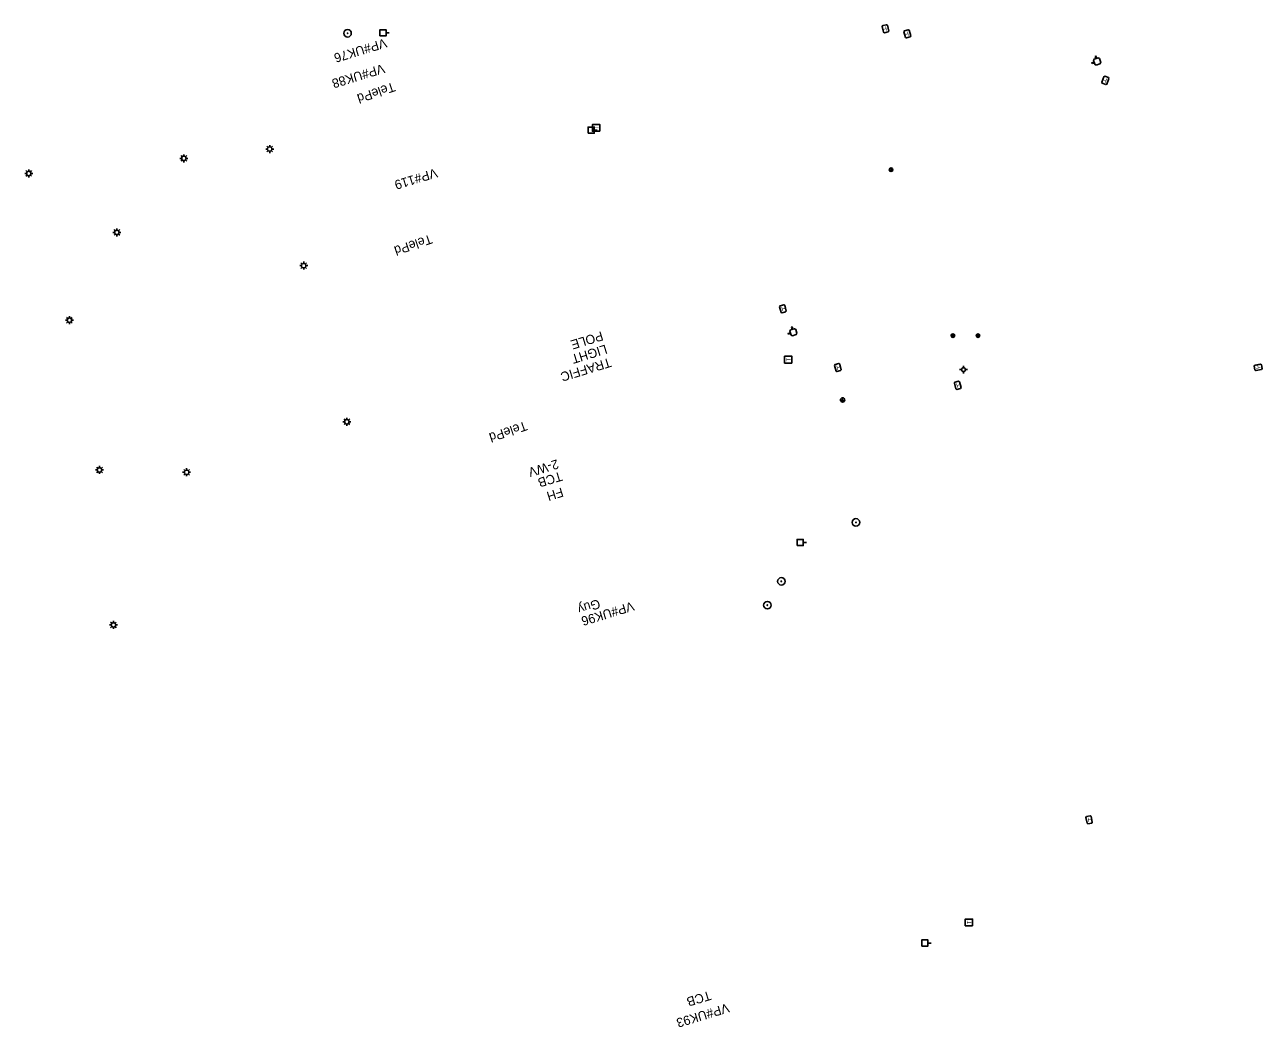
# Model space of a CAD drawing. Extents: x 3872070 to 3879223, y 293944 to 310567.
# Drawn here: x 3874077.6 to 3874479.2, y 307334.8 to 307660.2 of the extents above; entities that cross this region are included whole.
import ezdxf

# ---------------------------------------------------------------- set-up
doc = ezdxf.new("R2010")
doc.units = 0
for name, color, linetype in [('Level 34', 7, 'Continuous'), ('Level 35', 7, 'Continuous'), ('Level 37', 7, 'Continuous'), ('Level 39', 7, 'Continuous'), ('Level 4', 7, 'Continuous'), ('Level 5', 7, 'Continuous'), ('Level 6', 7, 'Continuous'), ('Level 7', 7, 'Continuous'), ('Level 9', 7, 'Continuous')]:
    doc.layers.add(name, color=color, linetype=linetype)

msp = doc.modelspace()

# ---------------------------------------------------------------- linework, layer by layer
at = {"layer": 'Level 4'}
for p, q in [((3874194.86, 307657.58), (3874195.86, 307657.58)), ((3874262.37, 307626.03), (3874263.37, 307626.03)), ((3874156.34, 307619.88), (3874155.77, 307619.88)), ((3874156.55, 307620.39), (3874156.15, 307620.8)), ((3874157.07, 307620.6), (3874157.07, 307621.18)), ((3874157.58, 307620.39), (3874157.98, 307620.8)), ((3874157.79, 307619.88), (3874158.37, 307619.88)), ((3874128.51, 307616.85), (3874127.93, 307616.85)), ((3874128.72, 307617.36), (3874128.31, 307617.77)), ((3874128.31, 307615.93), (3874128.72, 307616.33)), ((3874129.23, 307617.57), (3874129.23, 307618.15)), ((3874129.23, 307616.12), (3874129.23, 307615.55)), ((3874129.74, 307617.36), (3874130.15, 307617.77)), ((3874130.15, 307615.93), (3874129.74, 307616.33)), ((3874129.96, 307616.85), (3874130.53, 307616.85)), ((3874156.15, 307618.96), (3874156.55, 307619.37)), ((3874157.07, 307619.16), (3874157.07, 307618.58)), ((3874157.98, 307618.96), (3874157.58, 307619.37)), ((3874078.16, 307611.95), (3874077.58, 307611.95)), ((3874078.37, 307612.47), (3874077.96, 307612.87)), ((3874078.88, 307612.68), (3874078.88, 307613.25)), ((3874079.4, 307612.47), (3874079.8, 307612.87)), ((3874079.61, 307611.95), (3874080.18, 307611.95)), ((3874077.96, 307611.03), (3874078.37, 307611.44)), ((3874078.88, 307611.23), (3874078.88, 307610.65)), ((3874079.8, 307611.03), (3874079.4, 307611.44)), ((3874106.76, 307592.82), (3874106.19, 307592.82)), ((3874106.97, 307593.33), (3874106.57, 307593.74)), ((3874106.57, 307591.9), (3874106.97, 307592.3)), ((3874107.48, 307593.54), (3874107.48, 307594.12)), ((3874107.48, 307592.09), (3874107.48, 307591.52)), ((3874108, 307593.33), (3874108.4, 307593.74)), ((3874108.4, 307591.9), (3874108, 307592.3)), ((3874108.21, 307592.82), (3874108.79, 307592.82)), ((3874168.11, 307582.75), (3874168.11, 307583.33)), ((3874167.39, 307582.03), (3874166.81, 307582.03)), ((3874167.6, 307582.54), (3874167.19, 307582.95)), ((3874167.19, 307581.11), (3874167.6, 307581.52)), ((3874168.11, 307581.3), (3874168.11, 307580.73)), ((3874168.62, 307582.54), (3874169.03, 307582.95)), ((3874169.03, 307581.11), (3874168.62, 307581.52)), ((3874168.83, 307582.03), (3874169.41, 307582.03)), ((3874091.35, 307564.31), (3874090.78, 307564.31)), ((3874091.56, 307564.82), (3874091.16, 307565.23)), ((3874091.16, 307563.39), (3874091.56, 307563.79)), ((3874092.08, 307565.03), (3874092.08, 307565.61)), ((3874092.08, 307563.58), (3874092.08, 307563.01)), ((3874092.59, 307564.82), (3874093, 307565.23)), ((3874093, 307563.39), (3874092.59, 307563.79)), ((3874092.8, 307564.31), (3874093.38, 307564.31)), ((3874181.39, 307531.35), (3874180.81, 307531.35)), ((3874181.6, 307531.86), (3874181.2, 307532.27)), ((3874182.11, 307532.08), (3874182.11, 307532.65)), ((3874182.63, 307531.86), (3874183.03, 307532.27)), ((3874182.84, 307531.35), (3874183.41, 307531.35)), ((3874181.2, 307530.43), (3874181.6, 307530.84)), ((3874182.11, 307530.63), (3874182.11, 307530.05)), ((3874183.03, 307530.43), (3874182.63, 307530.84)), ((3874101.14, 307515.71), (3874100.56, 307515.71)), ((3874101.35, 307516.22), (3874100.94, 307516.62)), ((3874100.94, 307514.79), (3874101.35, 307515.19)), ((3874101.86, 307516.43), (3874101.86, 307517.01)), ((3874102.38, 307516.22), (3874102.78, 307516.62)), ((3874102.78, 307514.79), (3874102.38, 307515.19)), ((3874102.59, 307515.71), (3874103.16, 307515.71)), ((3874129.6, 307515.47), (3874129.19, 307515.87)), ((3874130.11, 307515.68), (3874130.11, 307516.25)), ((3874130.62, 307515.47), (3874131.03, 307515.87)), ((3874101.86, 307514.98), (3874101.86, 307514.41)), ((3874129.39, 307514.95), (3874128.81, 307514.95)), ((3874129.19, 307514.03), (3874129.6, 307514.44)), ((3874130.11, 307514.23), (3874130.11, 307513.65)), ((3874131.03, 307514.03), (3874130.62, 307514.44)), ((3874130.83, 307514.95), (3874131.41, 307514.95)), ((3874330.23, 307492.16), (3874331.23, 307492.16)), ((3874105.65, 307465.4), (3874105.08, 307465.4)), ((3874105.87, 307465.92), (3874105.46, 307466.32)), ((3874105.46, 307464.48), (3874105.87, 307464.89)), ((3874106.38, 307466.13), (3874106.38, 307466.7)), ((3874106.38, 307464.68), (3874106.38, 307464.1)), ((3874106.89, 307465.92), (3874107.3, 307466.32)), ((3874107.3, 307464.48), (3874106.89, 307464.89)), ((3874107.1, 307465.4), (3874107.68, 307465.4)), ((3874370.7, 307362.14), (3874371.7, 307362.14))]:
    msp.add_line(p, q, dxfattribs=at)
for points in [[(3874192.86, 307656.58), (3874192.86, 307658.58), (3874194.86, 307658.58), (3874194.86, 307656.58)], [(3874260.37, 307625.03), (3874260.37, 307627.03), (3874262.37, 307627.03), (3874262.37, 307625.03)], [(3874328.23, 307491.16), (3874328.23, 307493.16), (3874330.23, 307493.16), (3874330.23, 307491.16)], [(3874368.7, 307361.14), (3874368.7, 307363.14), (3874370.7, 307363.14), (3874370.7, 307361.14)]]:
    msp.add_lwpolyline(points, close=True, dxfattribs=at)
for centre, radius in [((3874182.34, 307657.46), 1.22), ((3874182.34, 307657.46), 0.0992), ((3874182.34, 307657.46), 0.0483), ((3874157.07, 307619.88), 0.725), ((3874129.23, 307616.85), 0.725), ((3874078.88, 307611.95), 0.725), ((3874107.48, 307592.82), 0.725), ((3874168.11, 307582.03), 0.725), ((3874092.08, 307564.31), 0.725), ((3874182.11, 307531.35), 0.725), ((3874101.86, 307515.71), 0.725), ((3874130.11, 307514.95), 0.725), ((3874347.33, 307498.68), 1.22), ((3874347.33, 307498.68), 0.0992), ((3874347.33, 307498.68), 0.0483), ((3874323.12, 307479.55), 1.22), ((3874323.12, 307479.55), 0.0992), ((3874323.12, 307479.55), 0.0483), ((3874318.58, 307471.82), 1.22), ((3874318.58, 307471.82), 0.0992), ((3874318.58, 307471.82), 0.0483), ((3874106.38, 307465.4), 0.725)]:
    msp.add_circle(centre, radius, dxfattribs=at)
at = {"layer": 'Level 5'}
for p, q in [((3874358.72, 307613.87), (3874358.72, 307613.15)), ((3874358.72, 307613.57), (3874358.72, 307612.73)), ((3874358.72, 307613.15), (3874358.72, 307612.43)), ((3874378.79, 307560.03), (3874378.79, 307559.31)), ((3874378.79, 307559.73), (3874378.79, 307558.89)), ((3874378.79, 307559.31), (3874378.79, 307558.59)), ((3874386.93, 307560.03), (3874386.93, 307559.31)), ((3874386.93, 307559.73), (3874386.93, 307558.89)), ((3874386.93, 307559.31), (3874386.93, 307558.59)), ((3874380.97, 307548.27), (3874381.59, 307548.27)), ((3874382.22, 307549.52), (3874382.22, 307548.89)), ((3874382.22, 307547.65), (3874382.22, 307547.02)), ((3874382.84, 307548.27), (3874383.47, 307548.27))]:
    msp.add_line(p, q, dxfattribs=at)
for centre, radius in [((3874358.73, 307613.15), 0.583), ((3874378.79, 307559.31), 0.583), ((3874386.94, 307559.31), 0.583), ((3874382.22, 307548.27), 0.625)]:
    msp.add_circle(centre, radius, dxfattribs=at)
for centre in [(3874358.73, 307613.15), (3874378.79, 307559.31), (3874386.94, 307559.31)]:
    msp.add_arc(centre, 0.417, 270, 90, dxfattribs=at)
at = {"layer": 'Level 6'}
for radius in [0.7, 0.188]:
    msp.add_circle((3874342.98, 307538.44), radius, dxfattribs=at)
at = {"layer": 'Level 7'}
for points in [[(3874264.22, 307625.65), (3874261.82, 307625.65), (3874261.82, 307627.84), (3874264.22, 307627.84)], [(3874326.56, 307550.41), (3874324.17, 307550.41), (3874324.17, 307552.6), (3874326.56, 307552.6)], [(3874385.17, 307367.74), (3874382.77, 307367.74), (3874382.77, 307369.93), (3874385.17, 307369.93)]]:
    msp.add_lwpolyline(points, close=True, dxfattribs=at)
at = {"layer": 'Level 9'}
for p, q in [((3874424.6, 307648.13), (3874423.86, 307647.9)), ((3874423.94, 307647.66), (3874423.86, 307647.9)), ((3874424.68, 307647.9), (3874423.94, 307647.66)), ((3874326.03, 307560.22), (3874325.29, 307559.98)), ((3874325.36, 307559.74), (3874325.29, 307559.98)), ((3874326.1, 307559.98), (3874325.36, 307559.75))]:
    msp.add_line(p, q, dxfattribs=at)
for points in [[(3874357.51, 307660.05), (3874357.95, 307658.19), (3874357.77, 307657.89), (3874356.58, 307657.6), (3874356.27, 307657.79), (3874355.83, 307659.64), (3874356.01, 307659.95), (3874357.21, 307660.23)], [(3874364.56, 307658.43), (3874365.08, 307656.59), (3874364.91, 307656.28), (3874363.73, 307655.95), (3874363.42, 307656.12), (3874362.9, 307657.95), (3874363.07, 307658.26), (3874364.25, 307658.6)], [(3874423.94, 307647.66), (3874424.68, 307647.89), (3874424.6, 307648.13), (3874423.86, 307647.9)], [(3874425.28, 307647.16), (3874426.51, 307647.55), (3874426.74, 307647.99), (3874426.36, 307649.23), (3874425.91, 307649.46), (3874424.68, 307649.07), (3874424.45, 307648.63), (3874424.84, 307647.4)], [(3874424.94, 307649.97), (3874425.18, 307649.23), (3874425.42, 307649.3), (3874425.18, 307650.05)], [(3874429.38, 307642.77), (3874428.74, 307640.97), (3874428.43, 307640.82), (3874427.27, 307641.23), (3874427.12, 307641.55), (3874427.75, 307643.35), (3874428.07, 307643.5), (3874429.23, 307643.09)], [(3874323.02, 307566.86), (3874322.53, 307568.7), (3874322.71, 307569.01), (3874323.89, 307569.32), (3874324.2, 307569.15), (3874324.69, 307567.3), (3874324.51, 307567), (3874323.33, 307566.68)], [(3874325.36, 307559.74), (3874326.11, 307559.98), (3874326.03, 307560.22), (3874325.29, 307559.98)], [(3874326.71, 307559.25), (3874327.94, 307559.64), (3874328.17, 307560.08), (3874327.78, 307561.31), (3874327.34, 307561.54), (3874326.11, 307561.16), (3874325.87, 307560.71), (3874326.26, 307559.48)], [(3874326.37, 307562.06), (3874326.6, 307561.31), (3874326.84, 307561.39), (3874326.61, 307562.13)], [(3874340.87, 307547.81), (3874340.37, 307549.65), (3874340.55, 307549.96), (3874341.73, 307550.28), (3874342.04, 307550.1), (3874342.53, 307548.26), (3874342.35, 307547.95), (3874341.17, 307547.64)], [(3874478.98, 307548.37), (3874477.11, 307547.98), (3874476.82, 307548.18), (3874476.57, 307549.38), (3874476.77, 307549.67), (3874478.63, 307550.06), (3874478.93, 307549.86), (3874479.17, 307548.66)], [(3874379.75, 307542.02), (3874379.25, 307543.86), (3874379.43, 307544.17), (3874380.61, 307544.49), (3874380.92, 307544.31), (3874381.42, 307542.47), (3874381.24, 307542.16), (3874380.06, 307541.85)], [(3874422.33, 307401.05), (3874421.96, 307402.93), (3874422.16, 307403.22), (3874423.36, 307403.46), (3874423.65, 307403.26), (3874424.02, 307401.39), (3874423.83, 307401.1), (3874422.62, 307400.86)]]:
    msp.add_lwpolyline(points, close=True, dxfattribs=at)

# ---------------------------------------------------------------- texts
at = {"layer": 'Level 34'}
for s, rotation, p in [('VP#UK76', 196.9281, (3874194.52, 307655.86)), ('VP#UK88', 196.9281, (3874193.85, 307647.56)), ('VP#119', 196.9281, (3874210.96, 307613.68)), ('Guy', 196.6305, (3874263.8, 307473.82)), ('VP#UK96', 196.9281, (3874274.78, 307473.05)), ('VP#UK93', 196.9281, (3874305.65, 307342.63))]:
    msp.add_text(s, height=3, rotation=rotation, dxfattribs=at).set_placement(p)
at = {"layer": 'Level 35'}
for s, p in [('2-WV', (3874250.28, 307519.18)), ('FH', (3874251.8, 307510.04))]:
    msp.add_text(s, height=3, rotation=197.2499, dxfattribs=at).set_placement(p)
at = {"layer": 'Level 37'}
for p in [(3874197.16, 307641.62), (3874209.2, 307592.22), (3874240, 307531.58)]:
    msp.add_text('TelePd', height=3, rotation=198.8135, dxfattribs=at).set_placement(p)
at = {"layer": 'Level 39'}
for s, rotation, p in [('POLE', 196.957, (3874264.73, 307560.76)), ('LIGHT', 196.957, (3874266.04, 307556.45)), ('TRAFFIC', 196.957, (3874267.35, 307552.15)), ('TCB', 196.9281, (3874251.48, 307515.2)), ('TCB', 196.9281, (3874299.76, 307346.67))]:
    msp.add_text(s, height=3, rotation=rotation, dxfattribs=at).set_placement(p)
at = {"layer": 'Level 7'}
for p in [(3874263.78, 307626.18), (3874326.14, 307550.93), (3874384.73, 307368.27)]:
    msp.add_text('T', height=1.41, rotation=90, dxfattribs=at).set_placement(p)
at = {"layer": 'Level 9'}
for rotation, p in [(193.5062, (3874357.18, 307659.71)), (195.9576, (3874364.24, 307658.08)), (160.5744, (3874428.92, 307642.67)), (15.0569, (3874323.34, 307567.2)), (15.0569, (3874341.18, 307548.16)), (101.6427, (3874478.65, 307548.71)), (15.0569, (3874380.07, 307542.37)), (11.1342, (3874422.67, 307401.38))]:
    msp.add_text('H', height=1.41, rotation=rotation, dxfattribs=at).set_placement(p)

doc.saveas('drawing.dxf')
